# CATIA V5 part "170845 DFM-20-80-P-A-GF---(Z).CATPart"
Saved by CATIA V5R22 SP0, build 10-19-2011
Part number: 170845 DFM-20-80-P-A-GF---(Z)
Property "ParasolidId": 3
Property "PSOL_INSTNR": 1
Bounding box of the stored display mesh (mm): x -121 to 0, y -17.05 to 19, z -41.5 to 41.5
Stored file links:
  U:\S9A\PER\CAO\Assemblage\Cadre\Chariot_Y\Prehenseur\170845 DFM-20-80-P-A-GF---(Z).CATPart
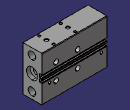
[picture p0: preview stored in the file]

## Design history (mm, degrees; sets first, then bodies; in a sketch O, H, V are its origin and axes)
Body1 "170845 DFM-20-80-P-A-GF---(Z)" (main body)
  Solid1: solid without history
